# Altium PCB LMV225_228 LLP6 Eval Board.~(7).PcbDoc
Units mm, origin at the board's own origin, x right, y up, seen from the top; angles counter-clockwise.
Board outline 50 x 55 mm, 2 copper layers (Top Layer, Bottom Layer); 17 components, 7 nets, 45 pads, 67 vias.
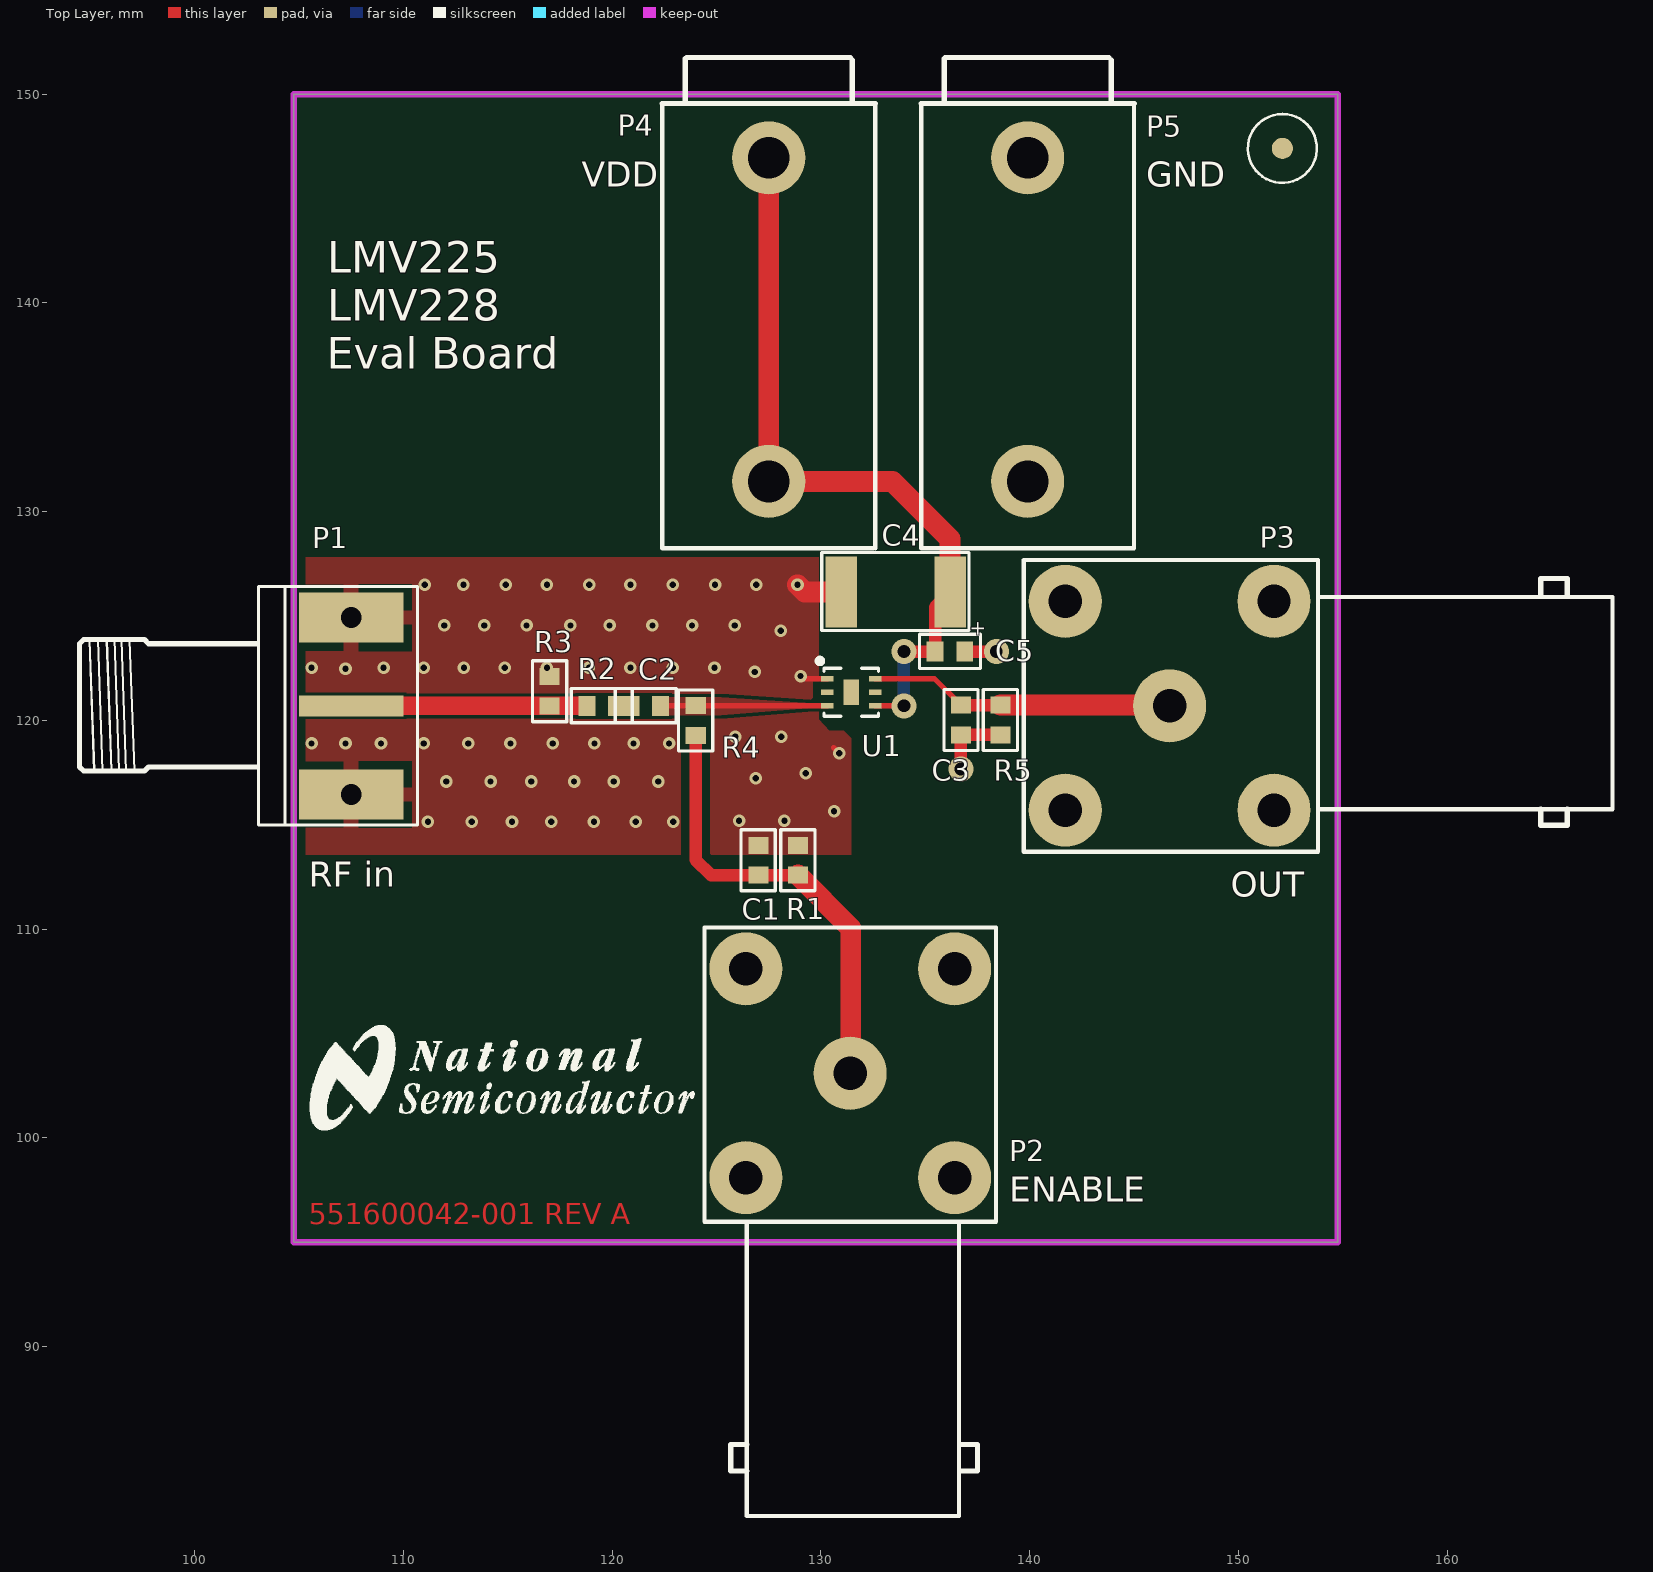
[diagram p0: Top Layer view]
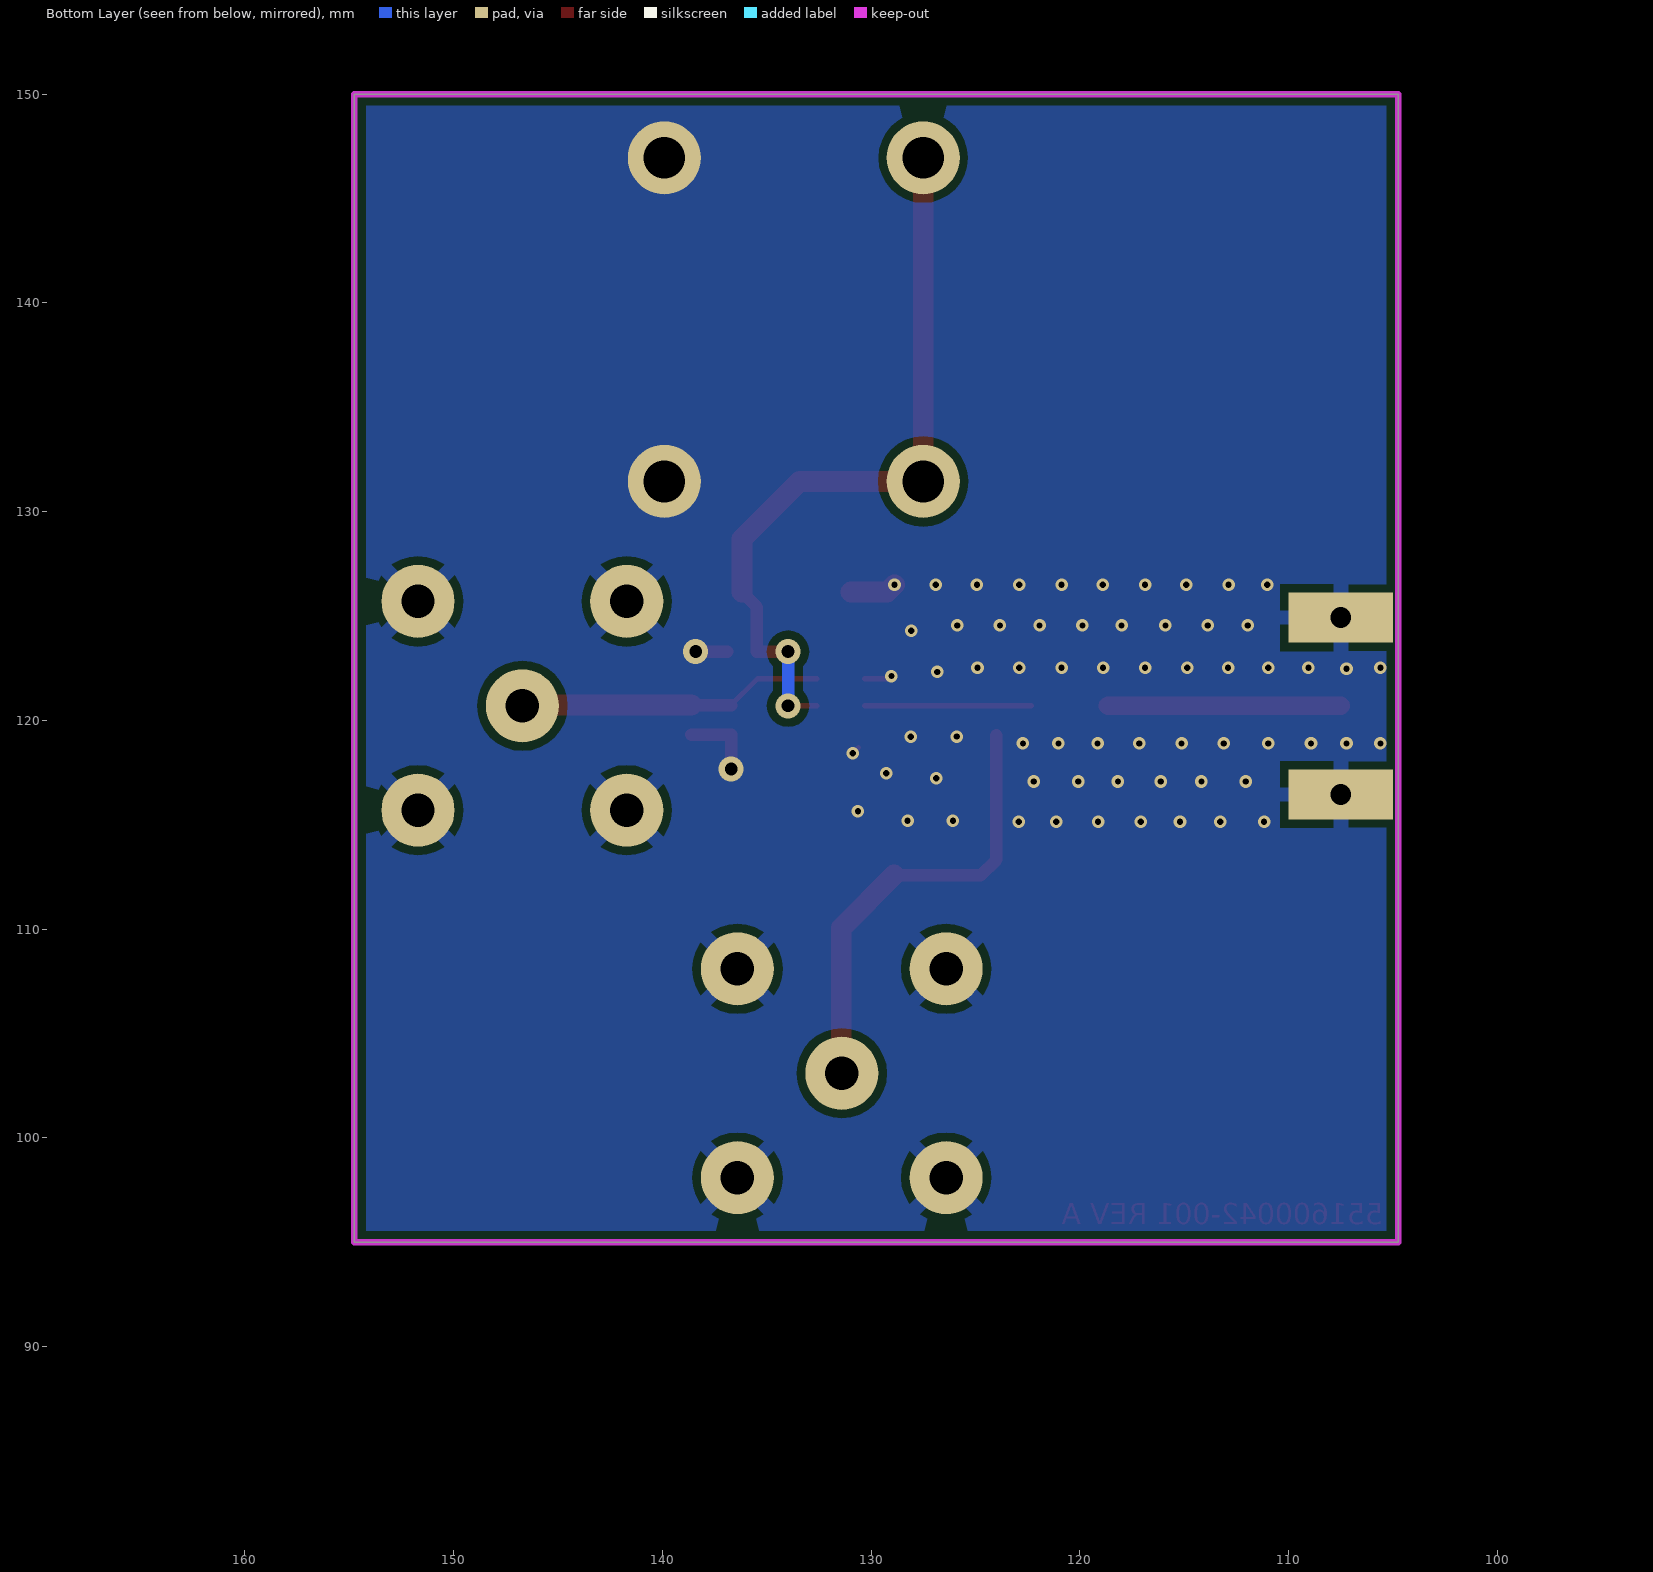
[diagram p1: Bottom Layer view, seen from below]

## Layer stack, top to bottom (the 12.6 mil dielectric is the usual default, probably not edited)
Top Layer: signal copper 0.0356
Dielectric: core 0.32, FR-4, Dk 4.8
Bottom Layer: signal copper 0.0356

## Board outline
104.75,95 154.75,95 154.75,150 104.75,150

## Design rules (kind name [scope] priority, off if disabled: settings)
Clearance Clearance_3 [InNet('NetC2_1')] p1: gap=0.15
Clearance Clearance_2 [InNet('NetC2_2')] p2: gap=0.15
Clearance Clearance_1 [InNet('NetP1_1')] p3: gap=0.15
Clearance [All] p4: gap=0.4
ComponentClearance [All] p1: gap=0.254 collisioncheckmode=3 verticalgap=0.254
PlaneConnect "Schematic Power Plane Connect Style" [InComponent('P4')] p1: planeconnectstyle=Relief reliefexpansion=0.762 reliefentries=4 reliefconductorwidth=0.5 reliefairgap=0.5
PlaneConnect "Schematic Power Plane Connect Style_1" [InComponent('P5')] p2: planeconnectstyle=Relief reliefexpansion=0.762 reliefentries=4 reliefconductorwidth=0.5 reliefairgap=0.5
PlaneConnect [All] p3: planeconnectstyle=Relief reliefexpansion=0.508 reliefentries=4 reliefconductorwidth=0.254 reliefairgap=0.254
PolygonConnect "Schematic Polygon Connect Style_1" [InComponent('P1')] p1: connectstyle=Relief reliefconductorwidth=0.7 reliefentries=4 polygonreliefangle="90 Angle"
PolygonConnect "Schematic Polygon Connect Style" [InComponent('P2')] p2: connectstyle=Relief reliefconductorwidth=0.7 reliefentries=4 polygonreliefangle="45 Angle"
PolygonConnect "Schematic Polygon Connect Style_2" [InComponent('P3')] p3: connectstyle=Relief reliefconductorwidth=0.7 reliefentries=4 polygonreliefangle="45 Angle"
PolygonConnect [All] p4: connectstyle=Direct reliefconductorwidth=0.254 reliefentries=4 polygonreliefangle="90 Angle"
RoutingVias [All] p1: holewidth=0.711 width=1.27 viastyle="Through Hole" minholewidth=0.711 minwidth=1.27 maxholewidth=0.711 maxwidth=1.27
SolderMaskExpansion [All] p1: expansion=0.102
TestPointUsage [All] p1: valid=0 allowmultiple=FALSE
Testpoint [All] p1: side=15 testpointundercomponent=TRUE minsize=1.016 maxsize=2.54 preferedsize=1.524 minholesize=0 maxholesize=1.016 preferedholesize=0.813 testpointgrid=0.025 style=1023 order=0-112345678
Width [All] p1: maxlimit=3 minlimit=0.2 preferedwidth=0.4
17 further rules are at their usual default settings.

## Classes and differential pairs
component class "LMV225_228 LLP6 Eval Board": C1 C2 C3 C4 C5 P1 P2 P3 P4 P5 R1 R2 R3 R4 R5 U1

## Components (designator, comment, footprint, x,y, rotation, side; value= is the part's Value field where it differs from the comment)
C1 "N/C" SM/RC_0603 127,113.3 r270 top
C2 "100p" SM/RC_0603 121.605,120.7 r180 top
C3 "N/C" SM/RC_0603 136.7,120.025 r90 top
C4 "100u" "CASE C" 133.575,126.15 r180 top
C5 "10n" SM/RC_0603 136.175,123.3 r180 top
P1 "RF in" SMA-SIDE 107.5,120.7 r0 top
P2 "ENABLE" BNC_RA 131.4,103.1 r90 top
P3 "V out" BNC_RA 146.7,120.7 r180 top
P4 "VDD" Banana_COLOR 127.5,139.2 r90 top
P5 "GND" Banana_COLOR 139.9,139.2 r90 top
R1 "N/C" SM/RC_0603 128.9,113.3 r270 top
R2 "0E" SM/RC_0603 119.5,120.7 r180 top
R3 "N/C" SM/RC_0603 117,121.4 r90 top
R4 "10k" SM/RC_0603 124,120 r270 top
R5 "N/C" SM/RC_0603 138.6,120.025 r270 top
U1 "LMV225_228_LLP6" SDB06A 131.45,121.35 r270 top
? "Comment" Fiducial 152.1,147.4 r0 top

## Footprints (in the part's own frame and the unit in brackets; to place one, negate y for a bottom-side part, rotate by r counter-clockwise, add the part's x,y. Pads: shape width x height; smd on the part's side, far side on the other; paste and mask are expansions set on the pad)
Banana_COLOR [mm] "Banana connector 6 colors"
  round 3.5 hole 2: 1(-7.75,0) 1(7.75,0)
  silkscreen extent -10.95,-5.1 12.55,5.1, body extent -10.86,-5 10.15,5.01, height 10
BNC_RA [mm]
  round 3.499 hole 1.6: 1(0,0) 2(-5,-5) 2(5,-5) 2(5,5)
  round 3.499 hole 1.6 paste+0: 2(-5,5)
  silkscreen extent -21.21,-6.98 6.98,6.98
"CASE C" [mm]
  rect 1.499x3.399 smd: 1(-2.61,0) 2(2.61,0)
  silkscreen extent -3.51,-1.9 3.53,1.85
Fiducial [mil]
  round 40 smd mask+40: 0(0,0)
  Top Overlay keep-out lines w5: 64.68,6.47 ccw(c0,0) 64.81,4.99
  silkscreen extent -65,-65 65,65
SDB06A [mm] "6-Pin LLP"
  rect 0.25x0.6 smd: 1(-0.65,-1.15) 2(0,-1.15) 3(0.65,-1.15) 4(0.65,1.15) 5(0,1.15) 6(-0.65,1.15)
  rect 1.2x0.75 smd: 7(0,0)
  silkscreen extent -1.62,-1.62 1.15,1.3, body extent -1.15,-1.3 1.15,1.3, height 0.8
SM/RC_0603 [mil]
  rect 32x38 smd: 1(-28,0) 2(28,0)
  silkscreen extent -58,-33 58,32
SMA-SIDE [mm]
  rect 5x1 smd: 1(0,0)
  rect 5x2.399 / inner round 1.524 / far side rect 5x2.399 hole 1: 2(0,-4.25) 2(0,4.225)
  silkscreen extent -13.01,-5.71 3.17,5.72, body extent -13.03,-5.74 2.5,5.74, height 4

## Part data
C1 C2 C3 C5: library part "C smd"
C4: library part "C tantaal"
P1: library part SMA, "SMA Connector"
P2 P3: library part BNC
P4 P5: library part "Banana socket"
R1 R2 R3 R4 R5: library part "R smd"
U1: library part LMV225_226_228_1, "LLP6"

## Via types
v1: diameter 0.6, hole 0.3, Top Layer to Bottom Layer, tented both sides, 62 vias
v2: diameter 1.2, hole 0.61, Top Layer to Bottom Layer, tented both sides, 2 vias
v3: diameter 1.2, hole 0.61, Top Layer to Bottom Layer, 2 vias
v4: diameter 0.6, hole 0.3, Top Layer to Bottom Layer, tented bottom, 1 vias

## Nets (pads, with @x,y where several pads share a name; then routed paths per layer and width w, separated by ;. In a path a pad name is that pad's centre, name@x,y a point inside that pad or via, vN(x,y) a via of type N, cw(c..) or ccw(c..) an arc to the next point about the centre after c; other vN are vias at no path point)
GND: C1.1 C3.1 C4.2 C5.1 P1.2 P2.2 P3.2 P5.1 R1.1 R3.2 R5.2 U1.1 | length 9
  Top Layer w0.25: v1(129.025,122.125) 129.15,122 U1.1 ; 130.6,118.7 v1(130.875,118.425)
  Top Layer w0.6: v2(136.7,117.675) C3.1 R5.2 ; C5.1 v2(138.4,123.3)
  Top Layer w1: v1(128.875,126.5) 129.225,126.15 C4.2
  other v1: 111.175,115.15 113.275,115.15 115.2,115.15 117.075,115.15 119.125,115.15 121.125,115.15 122.925,115.15 126.075,115.2 128.25,115.2 130.625,115.65 112.05,117.075 114.175,117.075 116.125,117.075 118.175,117.075 120.075,117.075 122.2,117.075 126.875,117.225 129.275,117.475 105.6,118.9 107.225,118.9 108.925,118.9 110.975,118.9 113.1,118.9 115.125,118.9 117.15,118.9 119.15,118.9 121.025,118.9 122.725,118.9 125.889,119.226 128.1,119.225 126.825,122.325 107.225,122.475 105.6,122.525 109.05,122.525 110.975,122.525 112.9,122.525 114.85,122.525 118.887,122.525 120.875,122.525 122.9,122.525 124.9,122.525 128.075,124.3 111.95,124.55 113.875,124.55 115.9,124.55 118,124.55 119.875,124.55 121.925,124.55 123.825,124.55 125.875,124.55 111.025,126.5 112.875,126.5 114.9,126.5 116.875,126.5 118.9,126.5 120.875,126.5 122.9,126.5 124.925,126.5 126.9,126.5
  other v4: 116.875,122.525
NetC1_2: C1.2 P2.1 R1.2 R4.2 | length 21.7
  Top Layer w0.6: R4.2 124,113.325 124.736,112.589 R1.2
  Top Layer w1: R1.2 131.4,110.089 ; P2.1@131.425,103.075 131.425,110.064
NetC2_1: C2.1 R4.1 U1.3 | length 8
  Top Layer w0.25: C2.1 U1.3
NetC2_2: C2.2 R2.1
NetC3_2: C3.2 P3.1 R5.1 U1.6 | length 14.6
  Top Layer w0.25: U1.6 135.436,122 C3.2
  Top Layer w0.6: C3.2 R5.1
  Top Layer w1: R5.1 146.664,120.736 P3.1
NetP1_1: P1.1 R2.2 R3.1 | length 11.1
  Top Layer w0.9: P1.1 R2.2@118.65,120.7
VDD: C4.1 C5.2 P4.1 U1.4 | length 36.5
  Top Layer w0.25: U1.4 v3(133.975,120.7)
  Top Layer w0.6: v3(133.975,123.3) C5.2 135.464,125.429 C4.1
  Top Layer w1: P4.1@127.5,146.95 127.5,131.45 133.425,131.45 136.185,128.69 C4.1
  Bottom Layer w0.6: v3(133.975,120.7) v3(133.975,123.3)
pads on no net: ?.0 U1.2 U1.5 U1.7

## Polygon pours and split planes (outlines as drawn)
NetC2_1 on Top Layer "220" (solid, pour order 0): 122.59,120.25 122.59,121.119 125.231,121.119 129.955,120.803 129.955,120.628 125.234,120.25
GND on Top Layer "221" (solid, pour order 1001): 131.442,113.573 105.044,113.573 105.023,127.808 129.882,127.808 129.882,120.047 130.405,119.511 131.096,119.511 131.442,119.153
GND on Bottom Layer "Bottom Layer-GND" (solid, remove dead copper, pour order 1000): 104.775,150 154.75,150 154.75,95.025 104.775,95.025

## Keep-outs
Keep-Out Layer:
  the board outline again, w0.3

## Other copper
Top Layer:
  pour cut-out: 123.267,119.945 124.733,119.945 124.738,120.088 123.25,120.088 123.25,120.075
  pour cut-out: 121.45,121.333 121.76,121.333 121.76,120.067 121.45,120.067
  pour cut-out: 119.345,121.333 119.655,121.333 119.655,120.067 119.345,120.067
  text "551600042-001 REV A" at 105.475,95.875 h1

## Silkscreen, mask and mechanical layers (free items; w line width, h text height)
Top Overlay:
  drawing of 24 lines, arcs and shapes, not listed
  text "VDD" at 118.55,145.575 h1.2
  text "GND" at 145.575,145.575 h1.2
  text "LMV225" at 106.35,141.45 h1.5
  text "LMV228" at 106.35,139.15 h1.5
  text "Eval Board" at 106.325,136.85 h1.5
  text "RF in" at 105.475,112.025 h1.2
  text "OUT" at 149.625,111.55 h1.2
  text "ENABLE" at 139.025,96.95 h1.2
Top Paste:
  text "881600042-001 REV A" at 84.175,91.675 h1
Bottom Paste:
  text "881600042-001 REV A" at 84.175,93.425 h1
Top Solder:
  text "551600042-001 REV A" at 105.475,95.875 h1
Bottom Solder:
  text "UL94V-0" at 153.775,98.975 h1
  text "MADE IN USA" at 153.775,97.487 h1
  text "(c)2007 NSC" at 153.775,96 h1
Drill Drawing:
  text ".Legend" at 179.8,79.1 h1.5

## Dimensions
154.75,150 to 154.75,95 on Mechanical 1
104.75,95 to 154.75,95 on Mechanical 1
